(* Logix 5000 project; controller Electronic_Displays vendor 1 type 14 code 65 rev 17.4; software revision 17.01; part 5 of 8 *)
(* tags used below, declared in another part *)
   ENVariable2Message : BOOL;   // 0 = don't setup variable 1 = setup variable
   ENVariable3Message : BOOL;   // 0 = don't setup variable 1 = setup variable
   ENVariable4Message : BOOL;   // 0 = don't setup variable 1 = setup variable
   Packet1Sent : STRING;   // The actual packet sent to the sign (Packet1)
   Packet2Sent : STRING;   // The actual packet sent to the sign (Packet2)
   Packet3Sent : STRING;   // The actual packet sent to the sign (Packet3)
   SEQ : DINT;   // Sequence Number
   InCycle : BOOL;   // Incycle
   SignETX : STRING;   // DO NOT EDIT = ^C
   SignSOH : STRING;   // DO NOT EDIT = ^A
   SignAddress : STRING;
   SignSTX : STRING;   // DO NOT EDIT = ^B
   SignVariable4 : STRING;
   SignVariable3 : STRING;
   SignVariable2 : STRING;
   SignSetMemoryCommand : STRING;   // DO NOT EDIT = SM
   SignCommandCode : STRING;   // DO NOT EDIT = C
   SignSizeVariableCommand : STRING;   // DO NOT EDIT = 0010 (16 bytes of memory) enough for 16 characters
   SignFileVariableCommand : STRING;   // DO NOT EDIT = V
   TotalPacketCount : DINT[7];   // Total Character Count
   Select : DINT;   // Packet Array Select
   PacketMax : DINT;   // Max Packet Count
   Packet3Offset : DINT;
   Packet2Offset : DINT;
   Packet1Offset : DINT;
   Packet : STRING[7];   // Packet Array to send to sign
(* SetupSignVariables, continued *)

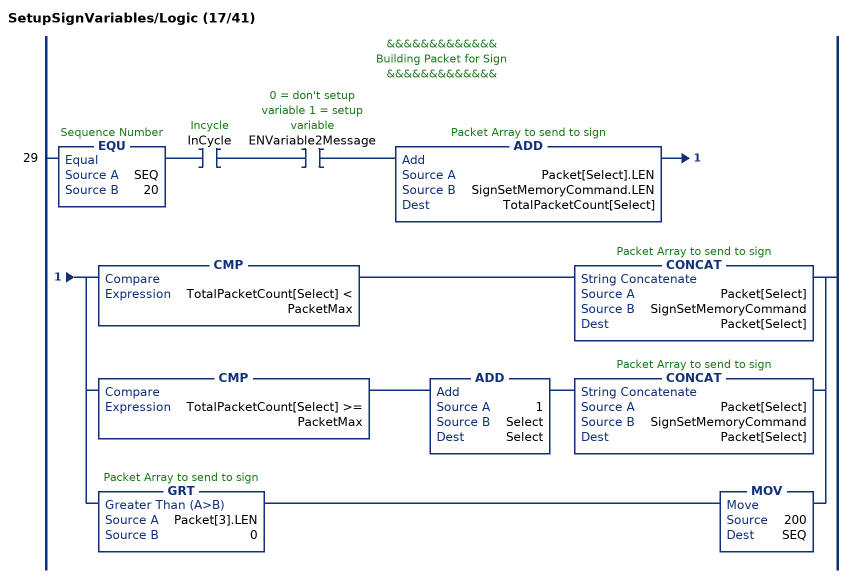
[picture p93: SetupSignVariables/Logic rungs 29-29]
   // &&&&&&&&&&&&&
   // Building Packet for Sign
   // &&&&&&&&&&&&&
   29: EQU(SEQ,20)XIC(InCycle)XIC(ENVariable2Message)ADD(Packet[Select].LEN,SignSetMemoryCommand.LEN,TotalPacketCount[Select])[CMP(TotalPacketCount[Select] < PacketMax) CONCAT(Packet[Select],SignSetMemoryCommand,Packet[Select]) ,CMP(TotalPacketCount[Select] >= PacketMax) ADD(1,Select,Select) CONCAT(Packet[Select],SignSetMemoryCommand,Packet[Select]) ,GRT(Packet[3].LEN,0) MOV(200,SEQ) ];
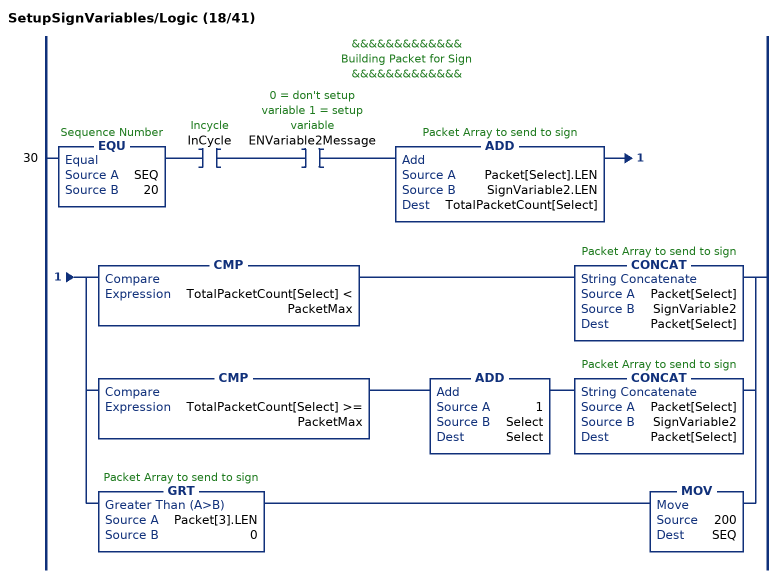
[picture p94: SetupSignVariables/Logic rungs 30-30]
   // &&&&&&&&&&&&&
   // Building Packet for Sign
   // &&&&&&&&&&&&&
   30: EQU(SEQ,20)XIC(InCycle)XIC(ENVariable2Message)ADD(Packet[Select].LEN,SignVariable2.LEN,TotalPacketCount[Select])[CMP(TotalPacketCount[Select] < PacketMax) CONCAT(Packet[Select],SignVariable2,Packet[Select]) ,CMP(TotalPacketCount[Select] >= PacketMax) ADD(1,Select,Select) CONCAT(Packet[Select],SignVariable2,Packet[Select]) ,GRT(Packet[3].LEN,0) MOV(200,SEQ) ];
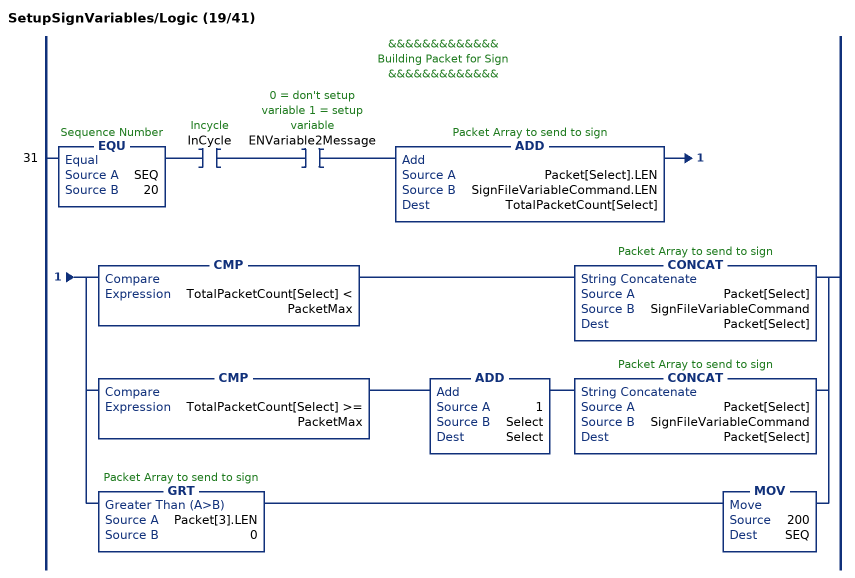
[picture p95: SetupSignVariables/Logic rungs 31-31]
   // &&&&&&&&&&&&&
   // Building Packet for Sign
   // &&&&&&&&&&&&&
   31: EQU(SEQ,20)XIC(InCycle)XIC(ENVariable2Message)ADD(Packet[Select].LEN,SignFileVariableCommand.LEN,TotalPacketCount[Select])[CMP(TotalPacketCount[Select] < PacketMax) CONCAT(Packet[Select],SignFileVariableCommand,Packet[Select]) ,CMP(TotalPacketCount[Select] >= PacketMax) ADD(1,Select,Select) CONCAT(Packet[Select],SignFileVariableCommand,Packet[Select]) ,GRT(Packet[3].LEN,0) MOV(200,SEQ) ];
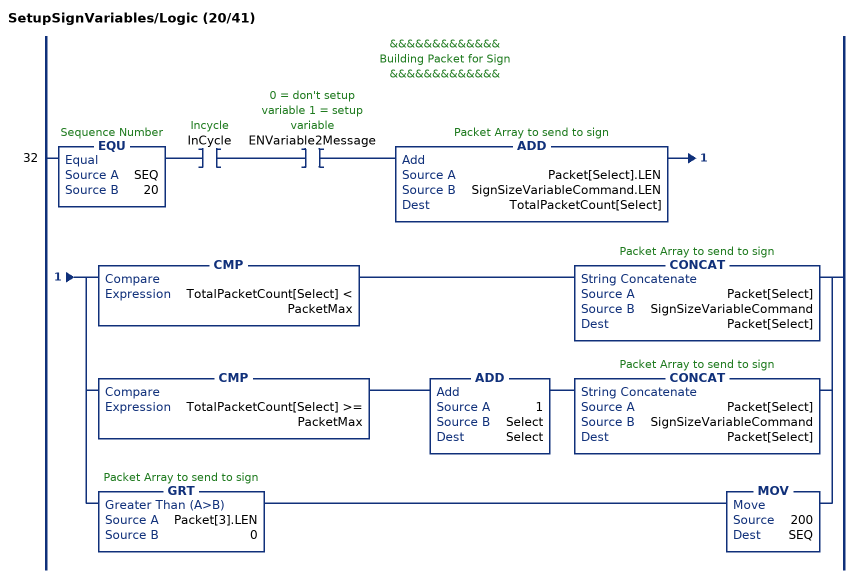
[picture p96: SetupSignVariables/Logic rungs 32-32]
   // &&&&&&&&&&&&&
   // Building Packet for Sign
   // &&&&&&&&&&&&&
   32: EQU(SEQ,20)XIC(InCycle)XIC(ENVariable2Message)ADD(Packet[Select].LEN,SignSizeVariableCommand.LEN,TotalPacketCount[Select])[CMP(TotalPacketCount[Select] < PacketMax) CONCAT(Packet[Select],SignSizeVariableCommand,Packet[Select]) ,CMP(TotalPacketCount[Select] >= PacketMax) ADD(1,Select,Select) CONCAT(Packet[Select],SignSizeVariableCommand,Packet[Select]) ,GRT(Packet[3].LEN,0) MOV(200,SEQ) ];
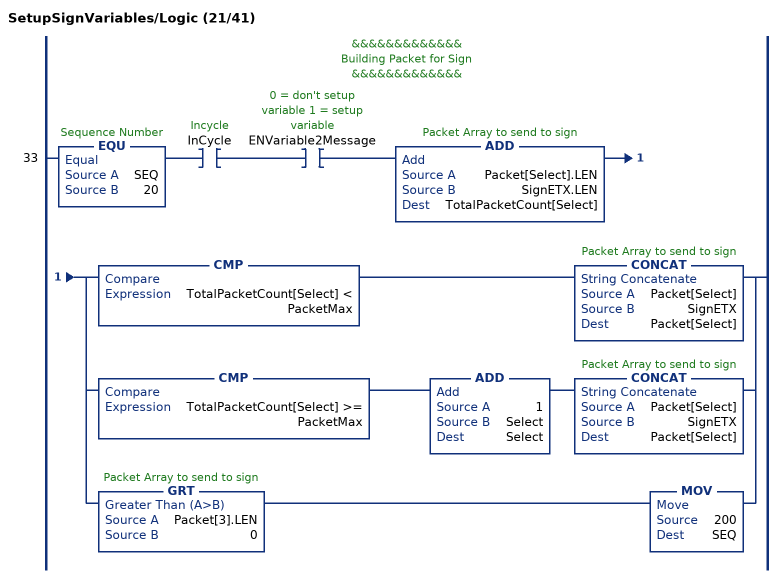
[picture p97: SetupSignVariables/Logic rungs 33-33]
   // &&&&&&&&&&&&&
   // Building Packet for Sign
   // &&&&&&&&&&&&&
   33: EQU(SEQ,20)XIC(InCycle)XIC(ENVariable2Message)ADD(Packet[Select].LEN,SignETX.LEN,TotalPacketCount[Select])[CMP(TotalPacketCount[Select] < PacketMax) CONCAT(Packet[Select],SignETX,Packet[Select]) ,CMP(TotalPacketCount[Select] >= PacketMax) ADD(1,Select,Select) CONCAT(Packet[Select],SignETX,Packet[Select]) ,GRT(Packet[3].LEN,0) MOV(200,SEQ) ];
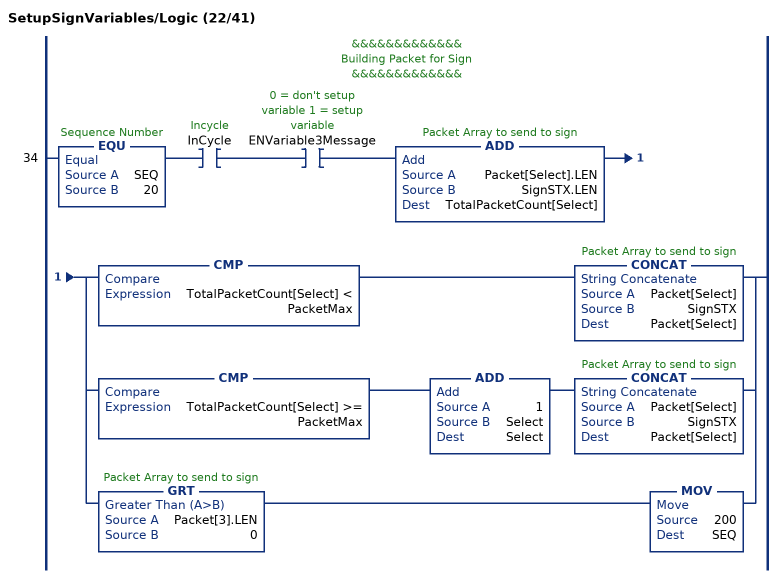
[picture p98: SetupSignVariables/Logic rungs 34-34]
   // &&&&&&&&&&&&&
   // Building Packet for Sign
   // &&&&&&&&&&&&&
   34: EQU(SEQ,20)XIC(InCycle)XIC(ENVariable3Message)ADD(Packet[Select].LEN,SignSTX.LEN,TotalPacketCount[Select])[CMP(TotalPacketCount[Select] < PacketMax) CONCAT(Packet[Select],SignSTX,Packet[Select]) ,CMP(TotalPacketCount[Select] >= PacketMax) ADD(1,Select,Select) CONCAT(Packet[Select],SignSTX,Packet[Select]) ,GRT(Packet[3].LEN,0) MOV(200,SEQ) ];
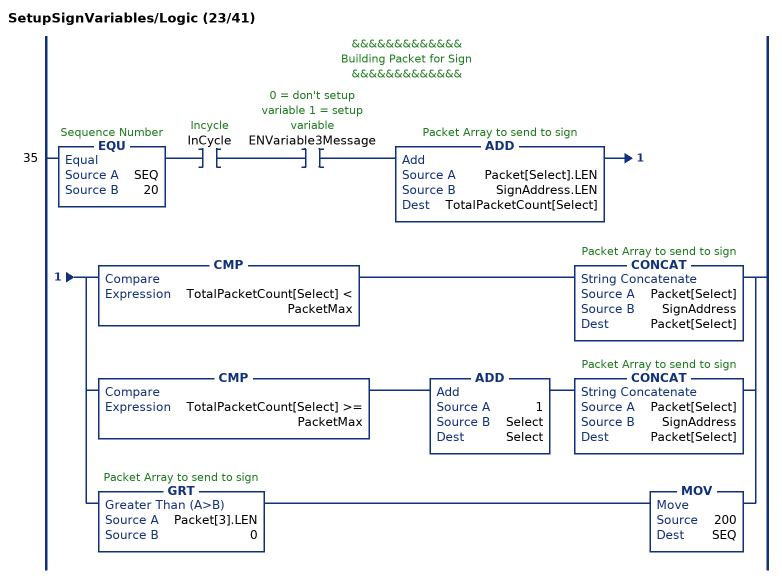
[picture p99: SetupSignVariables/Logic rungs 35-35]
   // &&&&&&&&&&&&&
   // Building Packet for Sign
   // &&&&&&&&&&&&&
   35: EQU(SEQ,20)XIC(InCycle)XIC(ENVariable3Message)ADD(Packet[Select].LEN,SignAddress.LEN,TotalPacketCount[Select])[CMP(TotalPacketCount[Select] < PacketMax) CONCAT(Packet[Select],SignAddress,Packet[Select]) ,CMP(TotalPacketCount[Select] >= PacketMax) ADD(1,Select,Select) CONCAT(Packet[Select],SignAddress,Packet[Select]) ,GRT(Packet[3].LEN,0) MOV(200,SEQ) ];
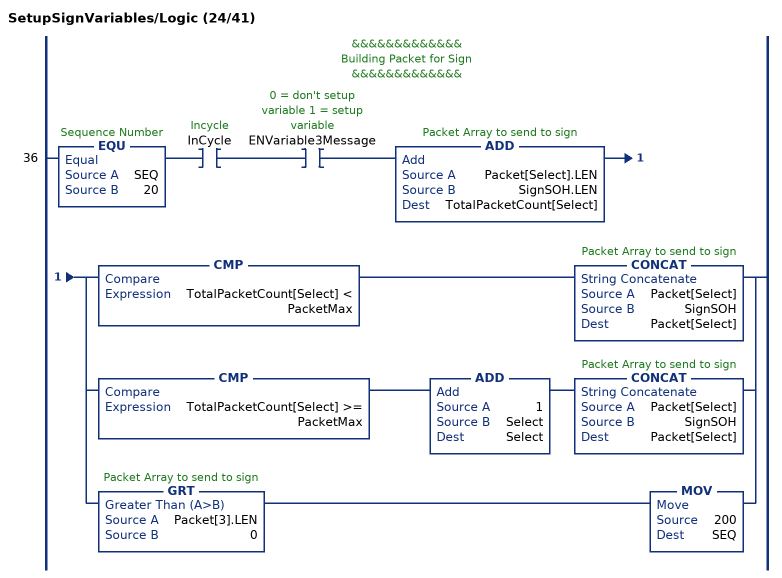
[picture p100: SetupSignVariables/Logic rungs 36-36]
   // &&&&&&&&&&&&&
   // Building Packet for Sign
   // &&&&&&&&&&&&&
   36: EQU(SEQ,20)XIC(InCycle)XIC(ENVariable3Message)ADD(Packet[Select].LEN,SignSOH.LEN,TotalPacketCount[Select])[CMP(TotalPacketCount[Select] < PacketMax) CONCAT(Packet[Select],SignSOH,Packet[Select]) ,CMP(TotalPacketCount[Select] >= PacketMax) ADD(1,Select,Select) CONCAT(Packet[Select],SignSOH,Packet[Select]) ,GRT(Packet[3].LEN,0) MOV(200,SEQ) ];
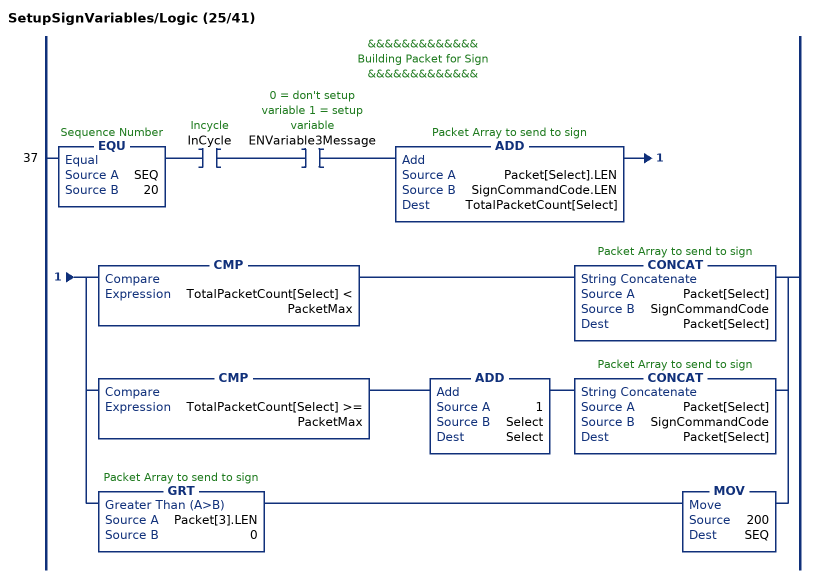
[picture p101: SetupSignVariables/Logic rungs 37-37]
   // &&&&&&&&&&&&&
   // Building Packet for Sign
   // &&&&&&&&&&&&&
   37: EQU(SEQ,20)XIC(InCycle)XIC(ENVariable3Message)ADD(Packet[Select].LEN,SignCommandCode.LEN,TotalPacketCount[Select])[CMP(TotalPacketCount[Select] < PacketMax) CONCAT(Packet[Select],SignCommandCode,Packet[Select]) ,CMP(TotalPacketCount[Select] >= PacketMax) ADD(1,Select,Select) CONCAT(Packet[Select],SignCommandCode,Packet[Select]) ,GRT(Packet[3].LEN,0) MOV(200,SEQ) ];
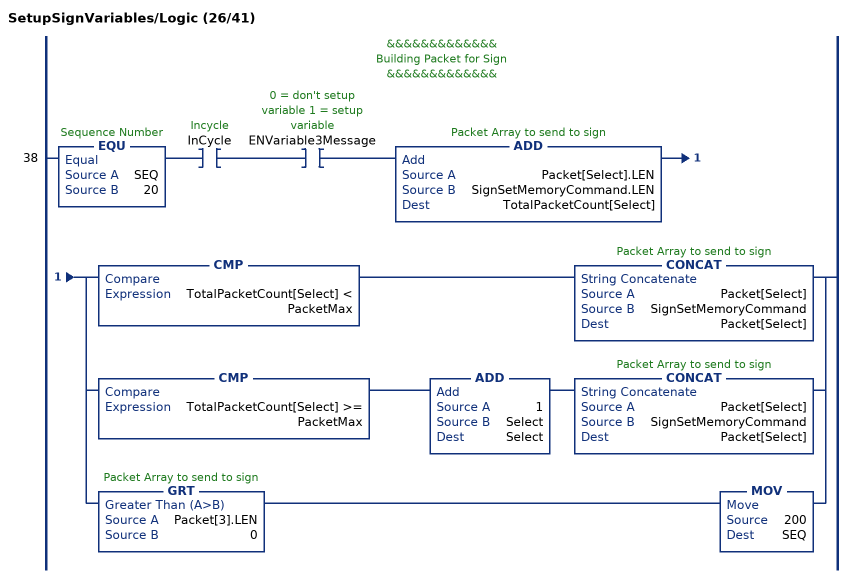
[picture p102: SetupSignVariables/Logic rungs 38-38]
   // &&&&&&&&&&&&&
   // Building Packet for Sign
   // &&&&&&&&&&&&&
   38: EQU(SEQ,20)XIC(InCycle)XIC(ENVariable3Message)ADD(Packet[Select].LEN,SignSetMemoryCommand.LEN,TotalPacketCount[Select])[CMP(TotalPacketCount[Select] < PacketMax) CONCAT(Packet[Select],SignSetMemoryCommand,Packet[Select]) ,CMP(TotalPacketCount[Select] >= PacketMax) ADD(1,Select,Select) CONCAT(Packet[Select],SignSetMemoryCommand,Packet[Select]) ,GRT(Packet[3].LEN,0) MOV(200,SEQ) ];
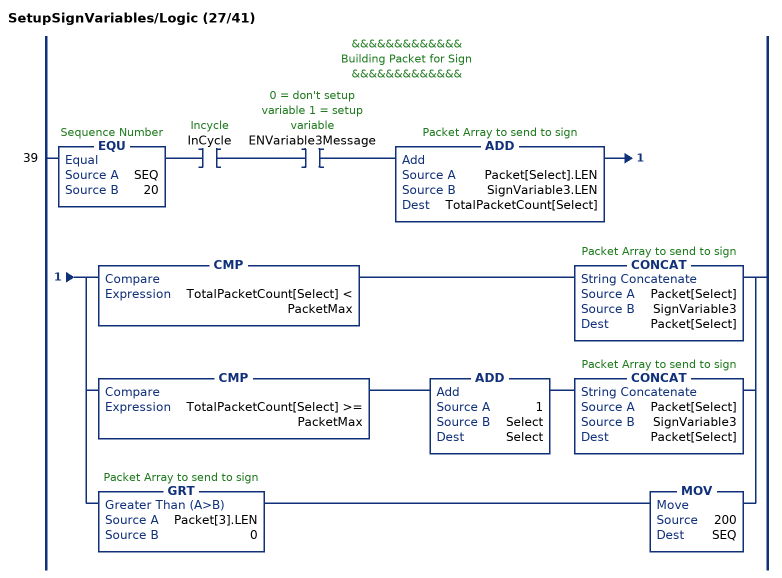
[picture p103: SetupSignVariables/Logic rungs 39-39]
   // &&&&&&&&&&&&&
   // Building Packet for Sign
   // &&&&&&&&&&&&&
   39: EQU(SEQ,20)XIC(InCycle)XIC(ENVariable3Message)ADD(Packet[Select].LEN,SignVariable3.LEN,TotalPacketCount[Select])[CMP(TotalPacketCount[Select] < PacketMax) CONCAT(Packet[Select],SignVariable3,Packet[Select]) ,CMP(TotalPacketCount[Select] >= PacketMax) ADD(1,Select,Select) CONCAT(Packet[Select],SignVariable3,Packet[Select]) ,GRT(Packet[3].LEN,0) MOV(200,SEQ) ];
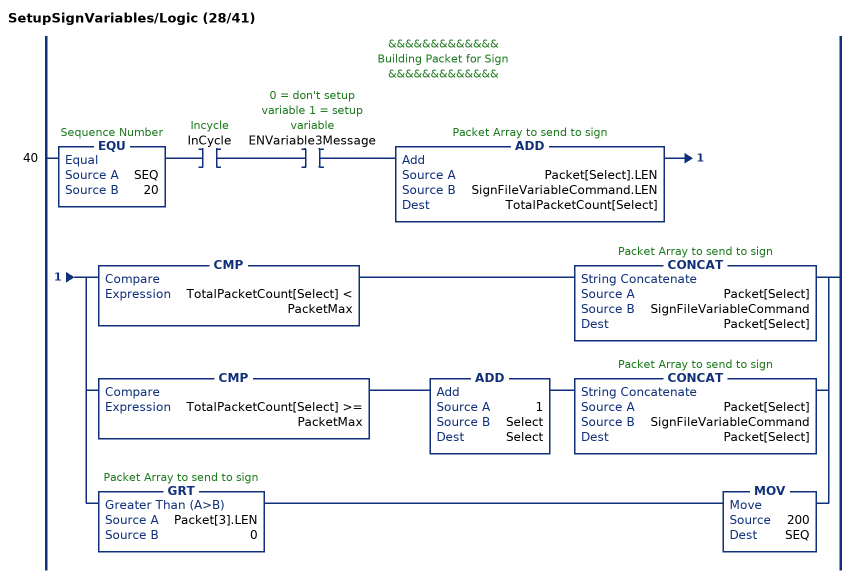
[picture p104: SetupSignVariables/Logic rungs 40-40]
   // &&&&&&&&&&&&&
   // Building Packet for Sign
   // &&&&&&&&&&&&&
   40: EQU(SEQ,20)XIC(InCycle)XIC(ENVariable3Message)ADD(Packet[Select].LEN,SignFileVariableCommand.LEN,TotalPacketCount[Select])[CMP(TotalPacketCount[Select] < PacketMax) CONCAT(Packet[Select],SignFileVariableCommand,Packet[Select]) ,CMP(TotalPacketCount[Select] >= PacketMax) ADD(1,Select,Select) CONCAT(Packet[Select],SignFileVariableCommand,Packet[Select]) ,GRT(Packet[3].LEN,0) MOV(200,SEQ) ];
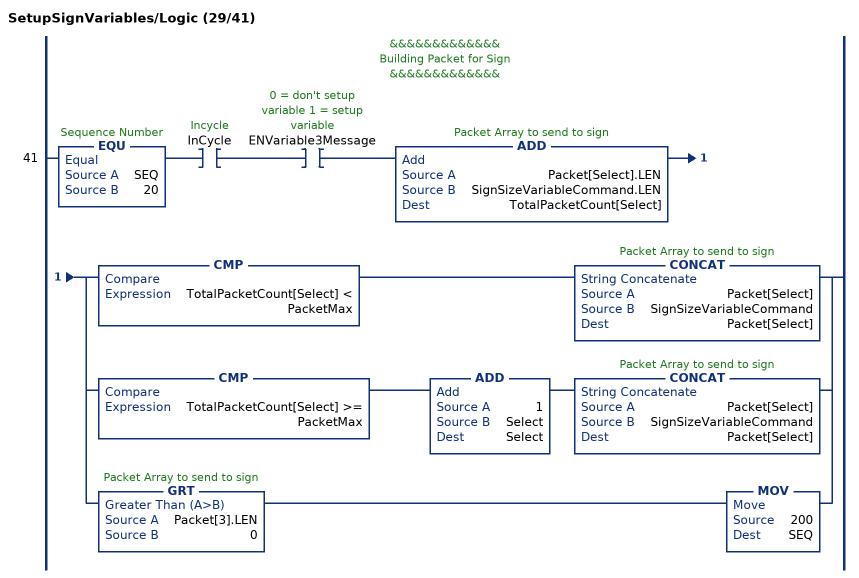
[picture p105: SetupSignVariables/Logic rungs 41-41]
   // &&&&&&&&&&&&&
   // Building Packet for Sign
   // &&&&&&&&&&&&&
   41: EQU(SEQ,20)XIC(InCycle)XIC(ENVariable3Message)ADD(Packet[Select].LEN,SignSizeVariableCommand.LEN,TotalPacketCount[Select])[CMP(TotalPacketCount[Select] < PacketMax) CONCAT(Packet[Select],SignSizeVariableCommand,Packet[Select]) ,CMP(TotalPacketCount[Select] >= PacketMax) ADD(1,Select,Select) CONCAT(Packet[Select],SignSizeVariableCommand,Packet[Select]) ,GRT(Packet[3].LEN,0) MOV(200,SEQ) ];
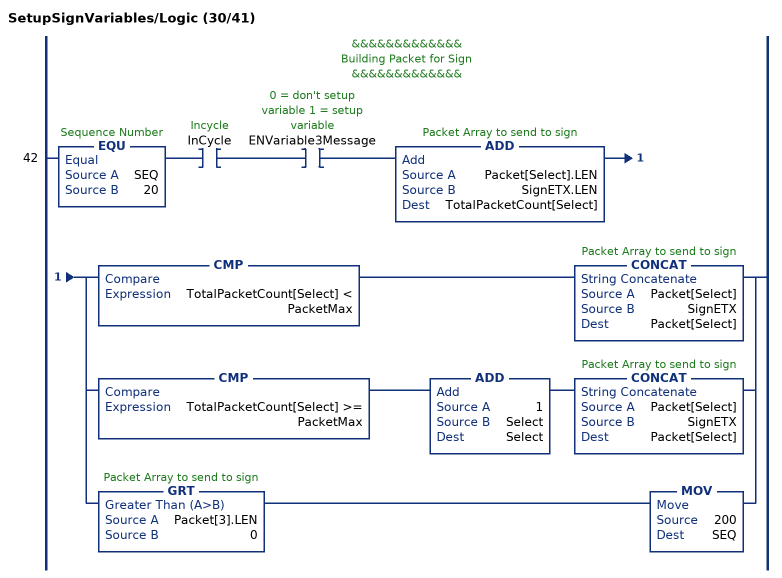
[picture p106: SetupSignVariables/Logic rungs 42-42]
   // &&&&&&&&&&&&&
   // Building Packet for Sign
   // &&&&&&&&&&&&&
   42: EQU(SEQ,20)XIC(InCycle)XIC(ENVariable3Message)ADD(Packet[Select].LEN,SignETX.LEN,TotalPacketCount[Select])[CMP(TotalPacketCount[Select] < PacketMax) CONCAT(Packet[Select],SignETX,Packet[Select]) ,CMP(TotalPacketCount[Select] >= PacketMax) ADD(1,Select,Select) CONCAT(Packet[Select],SignETX,Packet[Select]) ,GRT(Packet[3].LEN,0) MOV(200,SEQ) ];
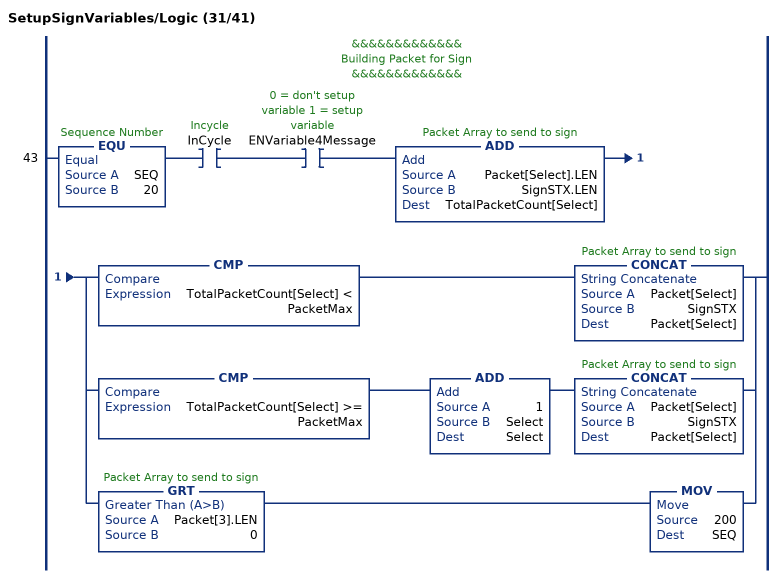
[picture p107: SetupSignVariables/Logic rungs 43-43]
   // &&&&&&&&&&&&&
   // Building Packet for Sign
   // &&&&&&&&&&&&&
   43: EQU(SEQ,20)XIC(InCycle)XIC(ENVariable4Message)ADD(Packet[Select].LEN,SignSTX.LEN,TotalPacketCount[Select])[CMP(TotalPacketCount[Select] < PacketMax) CONCAT(Packet[Select],SignSTX,Packet[Select]) ,CMP(TotalPacketCount[Select] >= PacketMax) ADD(1,Select,Select) CONCAT(Packet[Select],SignSTX,Packet[Select]) ,GRT(Packet[3].LEN,0) MOV(200,SEQ) ];
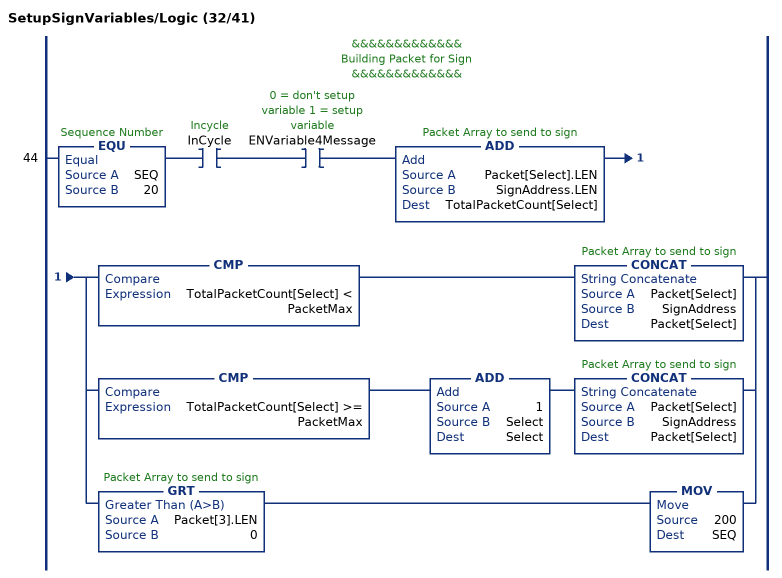
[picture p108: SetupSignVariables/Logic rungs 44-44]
   // &&&&&&&&&&&&&
   // Building Packet for Sign
   // &&&&&&&&&&&&&
   44: EQU(SEQ,20)XIC(InCycle)XIC(ENVariable4Message)ADD(Packet[Select].LEN,SignAddress.LEN,TotalPacketCount[Select])[CMP(TotalPacketCount[Select] < PacketMax) CONCAT(Packet[Select],SignAddress,Packet[Select]) ,CMP(TotalPacketCount[Select] >= PacketMax) ADD(1,Select,Select) CONCAT(Packet[Select],SignAddress,Packet[Select]) ,GRT(Packet[3].LEN,0) MOV(200,SEQ) ];
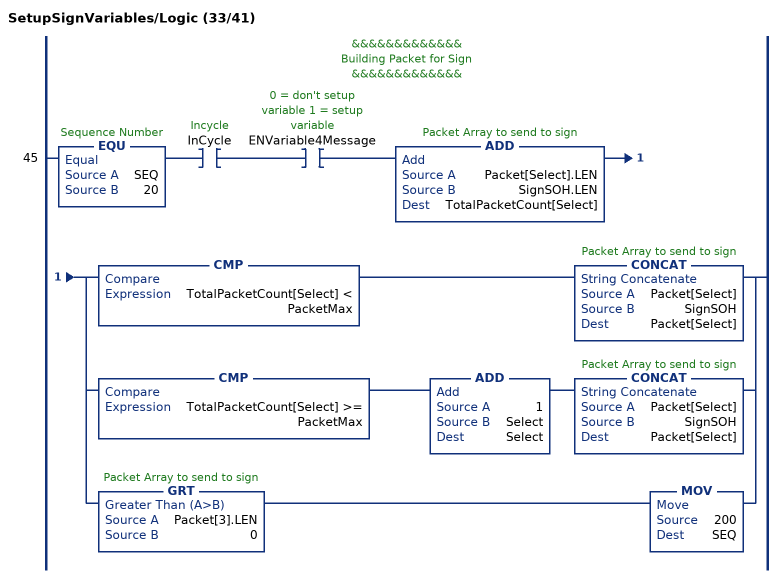
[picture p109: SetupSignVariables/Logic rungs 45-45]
   // &&&&&&&&&&&&&
   // Building Packet for Sign
   // &&&&&&&&&&&&&
   45: EQU(SEQ,20)XIC(InCycle)XIC(ENVariable4Message)ADD(Packet[Select].LEN,SignSOH.LEN,TotalPacketCount[Select])[CMP(TotalPacketCount[Select] < PacketMax) CONCAT(Packet[Select],SignSOH,Packet[Select]) ,CMP(TotalPacketCount[Select] >= PacketMax) ADD(1,Select,Select) CONCAT(Packet[Select],SignSOH,Packet[Select]) ,GRT(Packet[3].LEN,0) MOV(200,SEQ) ];
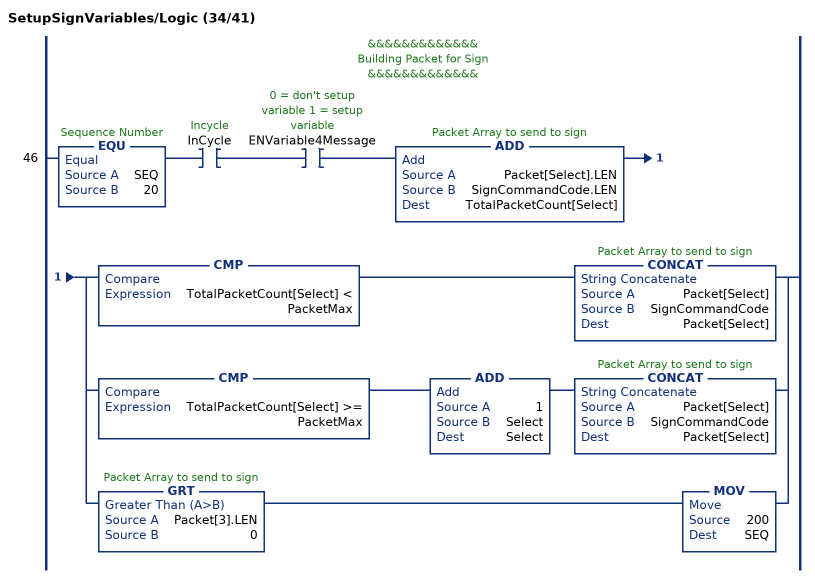
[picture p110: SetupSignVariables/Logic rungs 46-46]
   // &&&&&&&&&&&&&
   // Building Packet for Sign
   // &&&&&&&&&&&&&
   46: EQU(SEQ,20)XIC(InCycle)XIC(ENVariable4Message)ADD(Packet[Select].LEN,SignCommandCode.LEN,TotalPacketCount[Select])[CMP(TotalPacketCount[Select] < PacketMax) CONCAT(Packet[Select],SignCommandCode,Packet[Select]) ,CMP(TotalPacketCount[Select] >= PacketMax) ADD(1,Select,Select) CONCAT(Packet[Select],SignCommandCode,Packet[Select]) ,GRT(Packet[3].LEN,0) MOV(200,SEQ) ];
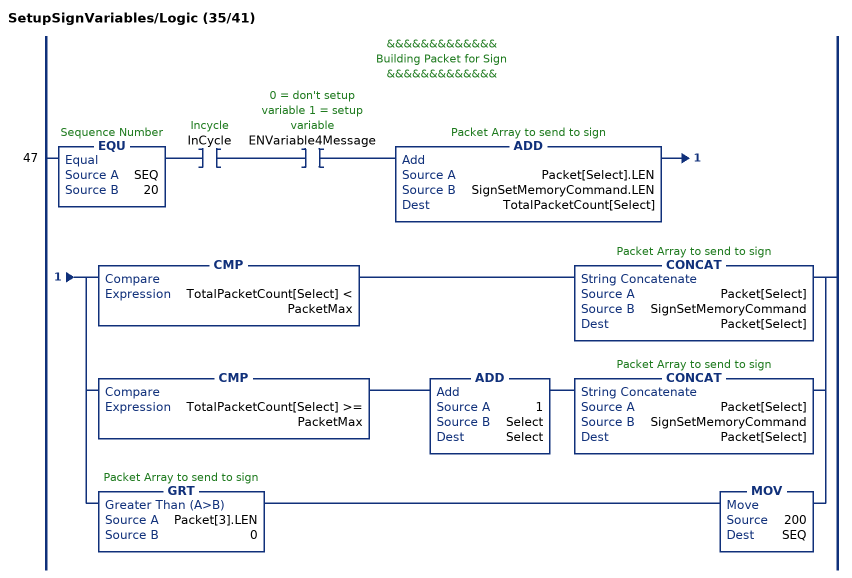
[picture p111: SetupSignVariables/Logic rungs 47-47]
   // &&&&&&&&&&&&&
   // Building Packet for Sign
   // &&&&&&&&&&&&&
   47: EQU(SEQ,20)XIC(InCycle)XIC(ENVariable4Message)ADD(Packet[Select].LEN,SignSetMemoryCommand.LEN,TotalPacketCount[Select])[CMP(TotalPacketCount[Select] < PacketMax) CONCAT(Packet[Select],SignSetMemoryCommand,Packet[Select]) ,CMP(TotalPacketCount[Select] >= PacketMax) ADD(1,Select,Select) CONCAT(Packet[Select],SignSetMemoryCommand,Packet[Select]) ,GRT(Packet[3].LEN,0) MOV(200,SEQ) ];
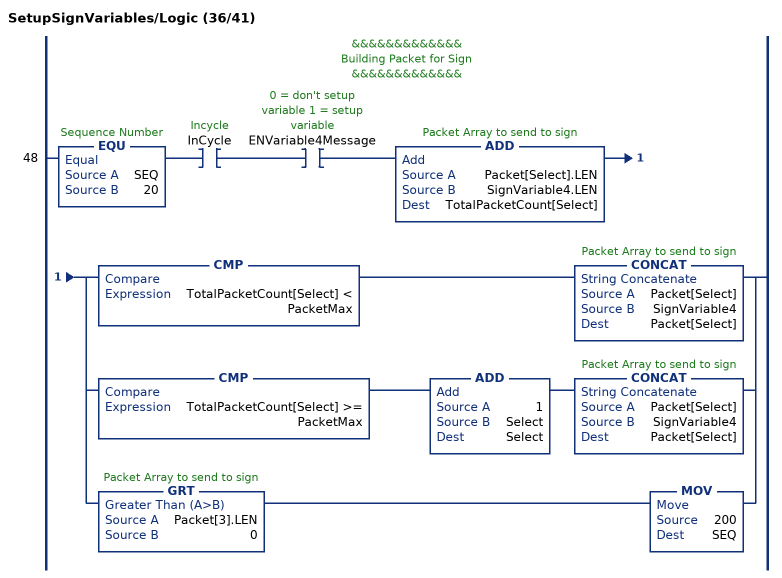
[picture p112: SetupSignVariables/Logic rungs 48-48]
   // &&&&&&&&&&&&&
   // Building Packet for Sign
   // &&&&&&&&&&&&&
   48: EQU(SEQ,20)XIC(InCycle)XIC(ENVariable4Message)ADD(Packet[Select].LEN,SignVariable4.LEN,TotalPacketCount[Select])[CMP(TotalPacketCount[Select] < PacketMax) CONCAT(Packet[Select],SignVariable4,Packet[Select]) ,CMP(TotalPacketCount[Select] >= PacketMax) ADD(1,Select,Select) CONCAT(Packet[Select],SignVariable4,Packet[Select]) ,GRT(Packet[3].LEN,0) MOV(200,SEQ) ];
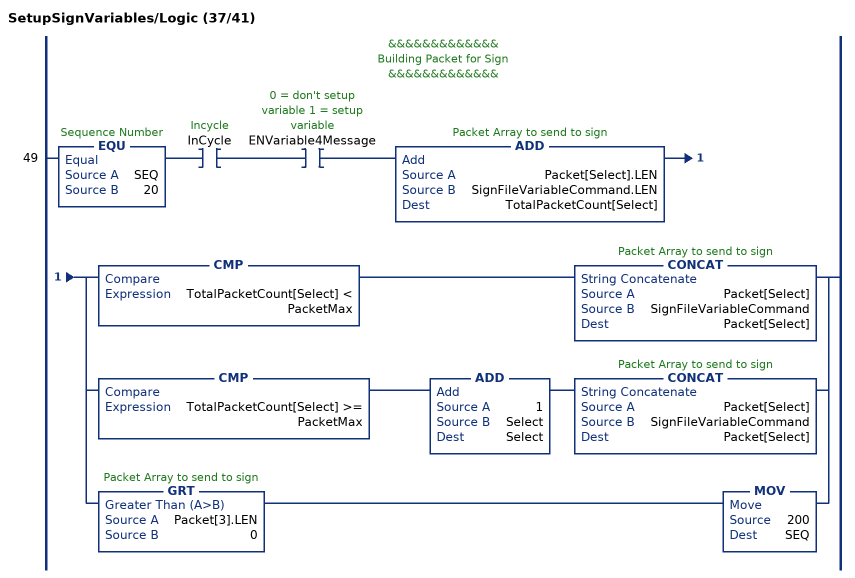
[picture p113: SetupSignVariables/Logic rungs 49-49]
   // &&&&&&&&&&&&&
   // Building Packet for Sign
   // &&&&&&&&&&&&&
   49: EQU(SEQ,20)XIC(InCycle)XIC(ENVariable4Message)ADD(Packet[Select].LEN,SignFileVariableCommand.LEN,TotalPacketCount[Select])[CMP(TotalPacketCount[Select] < PacketMax) CONCAT(Packet[Select],SignFileVariableCommand,Packet[Select]) ,CMP(TotalPacketCount[Select] >= PacketMax) ADD(1,Select,Select) CONCAT(Packet[Select],SignFileVariableCommand,Packet[Select]) ,GRT(Packet[3].LEN,0) MOV(200,SEQ) ];
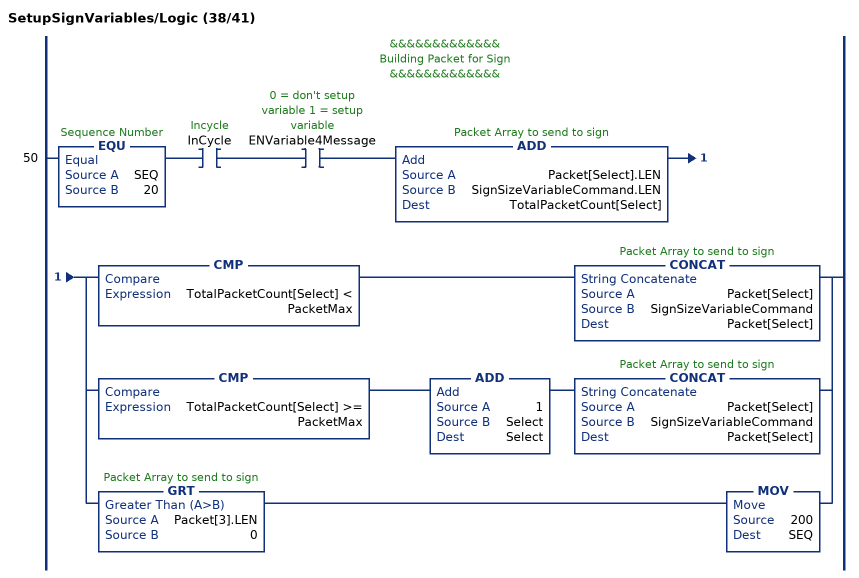
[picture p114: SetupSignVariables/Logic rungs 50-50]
   // &&&&&&&&&&&&&
   // Building Packet for Sign
   // &&&&&&&&&&&&&
   50: EQU(SEQ,20)XIC(InCycle)XIC(ENVariable4Message)ADD(Packet[Select].LEN,SignSizeVariableCommand.LEN,TotalPacketCount[Select])[CMP(TotalPacketCount[Select] < PacketMax) CONCAT(Packet[Select],SignSizeVariableCommand,Packet[Select]) ,CMP(TotalPacketCount[Select] >= PacketMax) ADD(1,Select,Select) CONCAT(Packet[Select],SignSizeVariableCommand,Packet[Select]) ,GRT(Packet[3].LEN,0) MOV(200,SEQ) ];
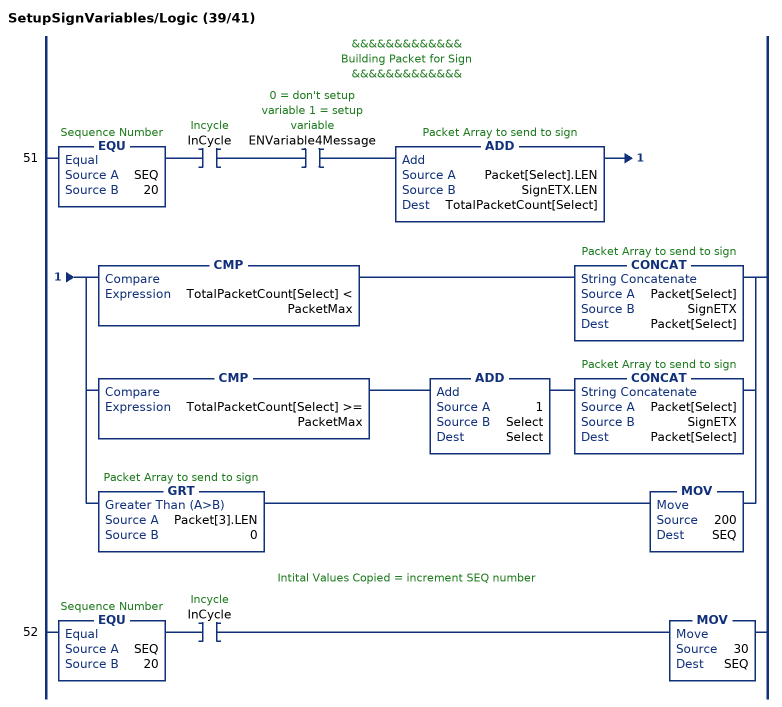
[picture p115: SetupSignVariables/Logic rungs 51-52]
   // &&&&&&&&&&&&&
   // Building Packet for Sign
   // &&&&&&&&&&&&&
   51: EQU(SEQ,20)XIC(InCycle)XIC(ENVariable4Message)ADD(Packet[Select].LEN,SignETX.LEN,TotalPacketCount[Select])[CMP(TotalPacketCount[Select] < PacketMax) CONCAT(Packet[Select],SignETX,Packet[Select]) ,CMP(TotalPacketCount[Select] >= PacketMax) ADD(1,Select,Select) CONCAT(Packet[Select],SignETX,Packet[Select]) ,GRT(Packet[3].LEN,0) MOV(200,SEQ) ];
   // Intital Values Copied = increment SEQ number
   52: EQU(SEQ,20)XIC(InCycle)MOV(30,SEQ);
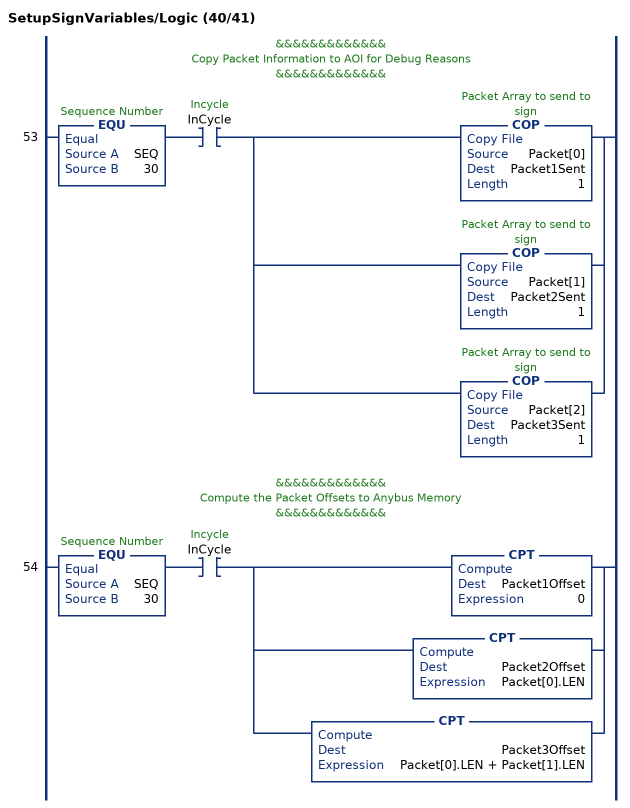
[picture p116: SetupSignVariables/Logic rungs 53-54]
   // &&&&&&&&&&&&&
   // Copy Packet Information to AOI for Debug Reasons
   // &&&&&&&&&&&&&
   53: EQU(SEQ,30)XIC(InCycle)[COP(Packet[0],Packet1Sent,1) ,COP(Packet[1],Packet2Sent,1) ,COP(Packet[2],Packet3Sent,1) ];
   // &&&&&&&&&&&&&
   // Compute the Packet Offsets to Anybus Memory
   // &&&&&&&&&&&&&
   54: EQU(SEQ,30)XIC(InCycle)[CPT(Packet1Offset,0) ,CPT(Packet2Offset,Packet[0].LEN) ,CPT(Packet3Offset,Packet[0].LEN + Packet[1].LEN) ];
